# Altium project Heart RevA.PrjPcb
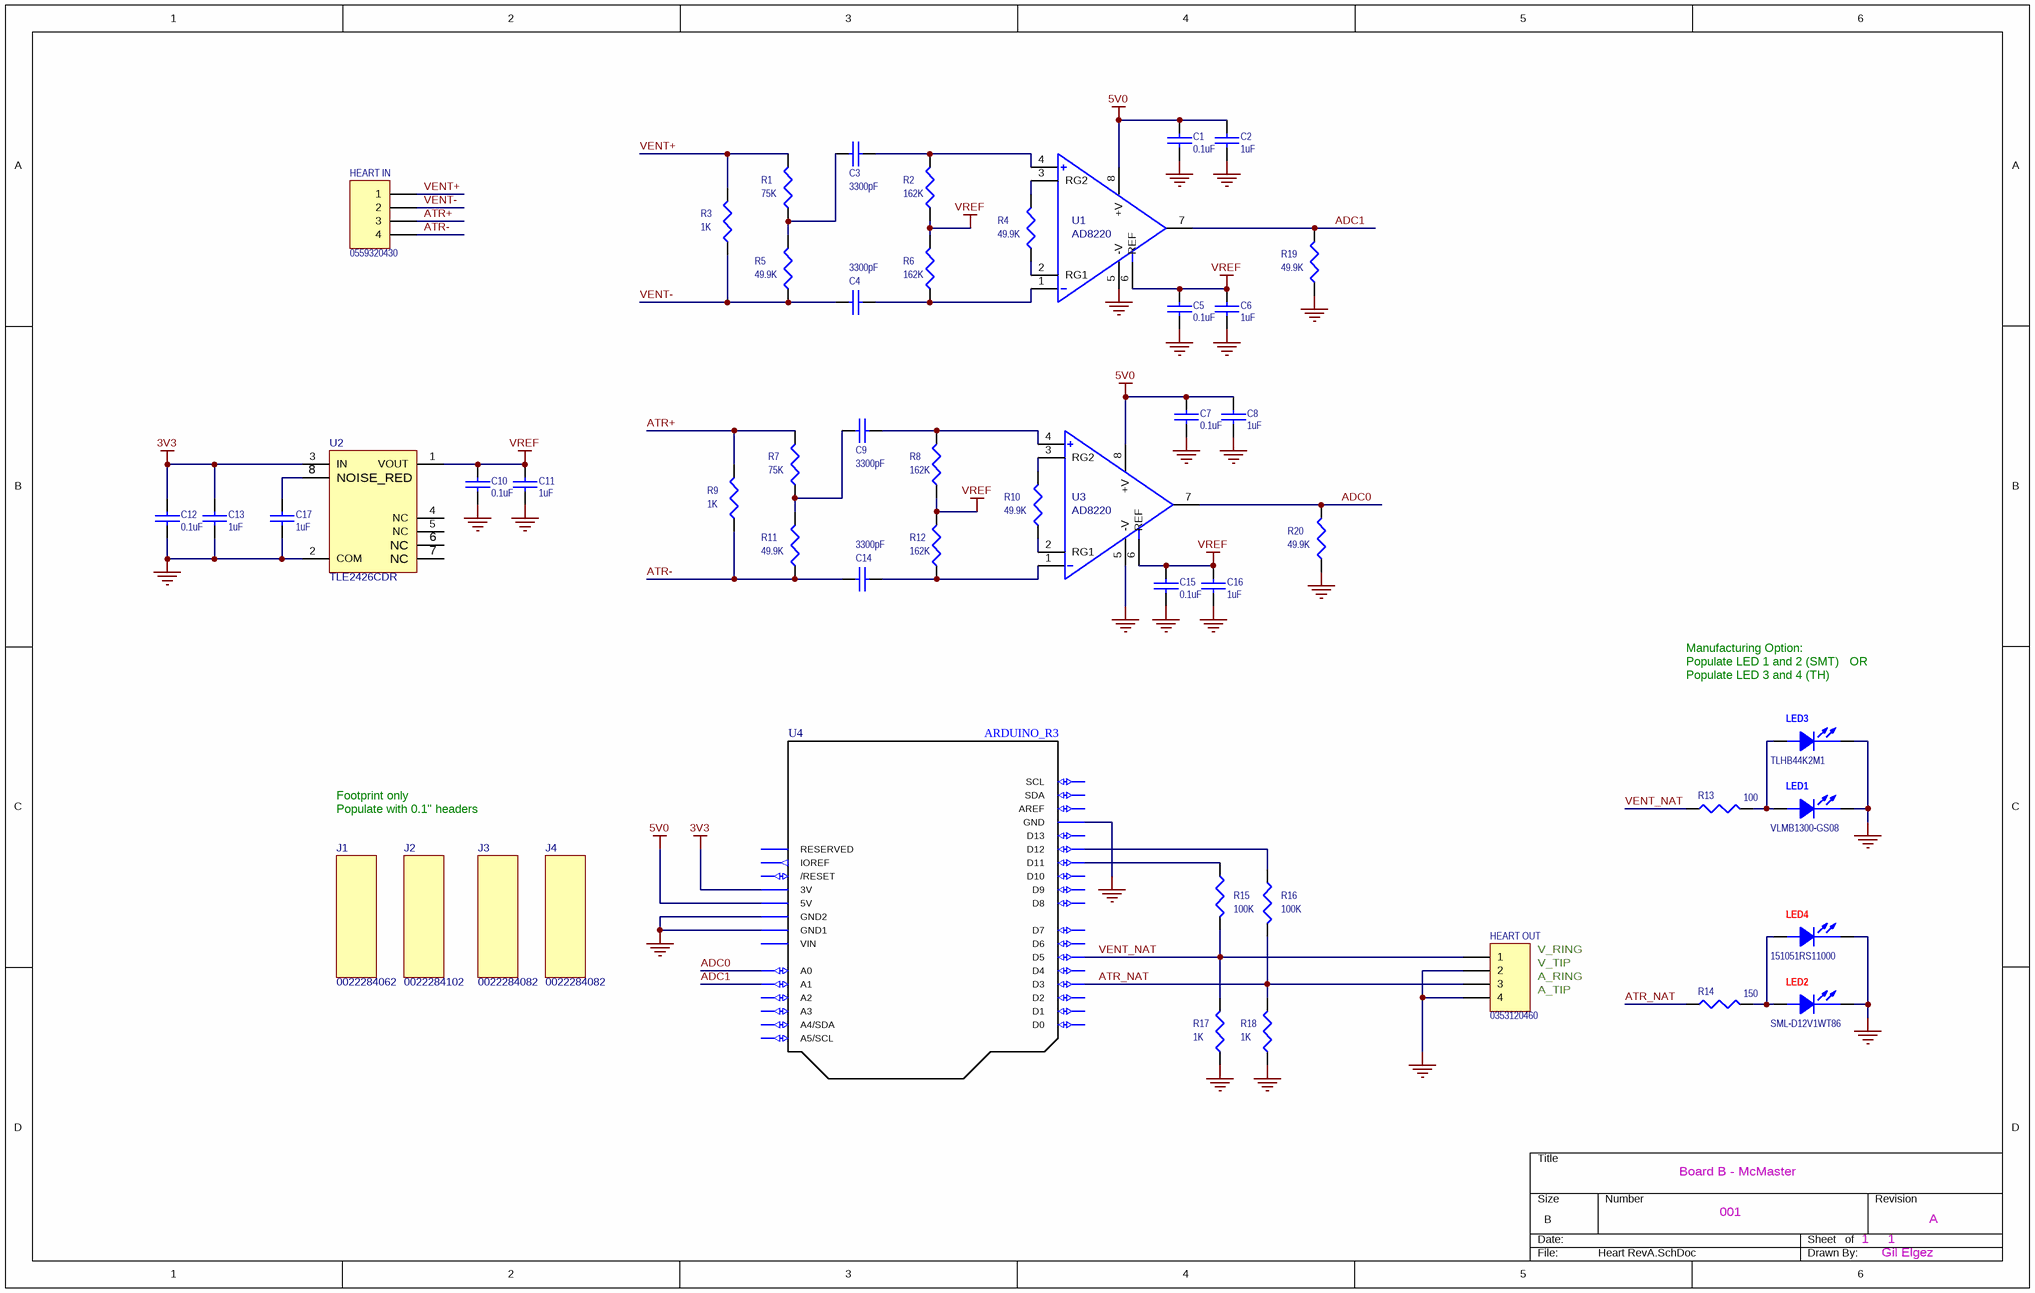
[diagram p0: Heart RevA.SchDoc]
1 sheet, 51 parts. Net scope: global (net labels, ports and power ports of the same name join across sheets).
Board file: Heart RevA.PcbDoc

## Sheet Heart RevA.SchDoc
size B; PageSetup: Record=PageOptions¦CenterHorizontal=True¦CenterVertical=True¦PrintScale=0.72¦XCorrection=1.00¦YCorrection=1.00¦PrintKind=0¦BorderSize=5000000¦LeftOffset=0¦BottomOffset=0¦Orientation=2¦PaperLength=1000¦PaperWidth=1000¦Scale=100¦PaperSource=7¦PrintQuality=-4¦MediaType=1¦DitherType=10¦PaperKind=Letter¦PrintScaleMode=1

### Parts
C1  0.1uF  [0603_N_1MM]
C2  1uF  [0603_N]
C3  3300pF  [0603_N]
C4  3300pF  [0603_N]
C5  0.1uF  [0603_N_1MM]
C6  1uF  [0603_N]
C7  0.1uF  [0603_N_1MM]
C8  1uF  [0603_N]
C9  3300pF  [0603_N]
C10  0.1uF  [0603_N_1MM]
C11  1uF  [0603_N]
C12  0.1uF  [0603_N_1MM]
C13  1uF  [0603_N]
C14  3300pF  [0603_N]
C15  0.1uF  [0603_N_1MM]
C16  1uF  [0603_N]
C17  1uF  [0603_N]
HEART_IN  0559320430  [B4B-PH-K-S]
HEART_OUT  0353120460  [B4B-XH-A]
J1  0022284062  [LHS-06-TS_OUTLINE]
J2  0022284102  [LHS-10-TS_OUTLINE]
J3  0022284082  [LHS-08-TS_OUTLINE]
J4  0022284082  [LHS-08-TS_OUTLINE]
LED1  VLMB1300-GS08  [LED_0603]
LED2  SML-D12V1WT86  [LED_0603]
LED3  TLHB44K2M1  [LED_5mm]
LED4  151051RS11000  [LED_5mm]
R1  75K  [0603_N_RES]
R2  162K  [0603_N_RES]
R3  1K  [0603_N_RES]
R4  49.9K  [0603_N_RES]
R5  49.9K  [0603_N_RES]
R6  162K  [0603_N_RES]
R7  75K  [0603_N_RES]
R8  162K  [0603_N_RES]
R9  1K  [0603_N_RES]
R10  49.9K  [0603_N_RES]
R11  49.9K  [0603_N_RES]
R12  162K  [0603_N_RES]
R13  100  [0603_N_RES]
R14  150  [0603_N_RES]
R15  100K  [0603_N_RES]
R16  100K  [0603_N_RES]
R17  1K  [0603_N_RES]
R18  1K  [0603_N_RES]
R19  49.9K  [0603_N_RES]
R20  49.9K  [0603_N_RES]
U1  AD8220  [MSOP8_0.65mm_DGK]
U2  TLE2426CDR  [SOIC8_SMTC]
U3  AD8220  [MSOP8_0.65mm_DGK]
U4  ARDUINO_R3  [ARDUINOR3]

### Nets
3V3: C12.2 C13.2 U2.3(IN) U4.3V
5V0: C1.2 C2.2 C7.2 C8.2 U1.8(+V) U3.8(+V) U4.5V
GND: C1.1 C2.1 C5.1 C6.1 C7.1 C8.1 C10.1 C11.1 C12.1 C13.1 C15.1 C16.1 C17.1 HEART_OUT.2 HEART_OUT.4 LED1.K(CATHODE) LED2.K(CATHODE) LED3.K(CATHODE) LED4.K(CATHODE) R17.1 R18.1 R19.1 R20.1 U1.5(-V) U2.2(COM) U3.5(-V) U4.GND U4.GND1 U4.GND2
VREF: C5.2 C6.2 C10.2 C11.2 C15.2 C16.2 R2.1 R6.2 R8.1 R12.2 U1.6(REF) U2.1(VOUT) U3.6(REF)
ADC0: R20.2 U3.7(OUT) U4.A0
ADC1: R19.2 U1.7(OUT) U4.A1
ATR+: HEART_IN.3 R7.2 R9.2
ATR-: C14.1 HEART_IN.4 R9.1 R11.1
ATR_NAT: HEART_OUT.3 R14.1 R16.2 R18.2 U4.D3
VENT+: HEART_IN.1 R1.2 R3.2
VENT-: C4.1 HEART_IN.2 R3.1 R5.1
VENT_NAT: HEART_OUT.1 R13.1 R15.2 R17.2 U4.D5
NetC3_1: C3.1 R1.1 R5.2
NetC3_2: C3.2 R2.2 U1.4(+IN)
NetC4_2: C4.2 R6.1 U1.1(-IN)
NetC9_1: C9.1 R7.1 R11.2
NetC9_2: C9.2 R8.2 U3.4(+IN)
NetC14_2: C14.2 R12.1 U3.1(-IN)
NetC17_2: C17.2 U2.8(NOISE_RED)
NetLED1_A: LED1.A(ANODE) LED3.A(ANODE) R13.2
NetLED2_A: LED2.A(ANODE) LED4.A(ANODE) R14.2
NetR4_1: R4.1 U1.2(RG1)
NetR4_2: R4.2 U1.3(RG2)
NetR10_1: R10.1 U3.2(RG1)
NetR10_2: R10.2 U3.3(RG2)
NetR15_1: R15.1 U4.D11
NetR16_1: R16.1 U4.D12

Not connected (* = marked no-connect by the designer): U2 4(NC) 5(NC) 6(NC) 7(NC); U4 A2 A3 A4(A4/SDA) A5(A5/SCL) AREF D0 D1 D2 D4 D6 D7 D8 D9 D10 D13 IOREF RESERVED RESET(/RESET) SCL SDA VIN

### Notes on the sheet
- (near LED3) Manufacturing Option:
  Populate LED 1 and 2 (SMT)   OR
  Populate LED 3 and 4 (TH)
- Footprint only
  Populate with 0.1" headers
- (near HEART_OUT) V_RING
- (near HEART_OUT) V_TIP
- (near HEART_OUT) A_RING
- (near HEART_OUT) A_TIP
- Board B - McMaster
- 001
- 1     1
- A
- Gil Elgez

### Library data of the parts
C1 C5 C7 C10 C12 C15 = CAP: CAP CER 0.1UF 50V X7R 0603; Manufacturer: Samsung; Value: CL10B104KB8NNNL
C2 C6 C8 C11 C13 C16 C17 = CAP: CAP CER 1UF 6.3V X7R 0603; Manufacturer: Samsung; Value: CL10B105KQ8NNNC
C3 C4 C9 C14 = CAP: CAP CER 3300PF 10V C0G/NP0 0603; Manufacturer: Würth Elektronik; Value: 885012006016
HEART_IN = Header 4: CONN HEADER VERT 4POS 2MM; Manufacturer: Molex
HEART_OUT = Header 4: CONN HEADER VERT 4POS 2.5MM; Manufacturer: Molex
J1 = SIP Header 6 Outline: CONN HEADER VERT 6POS 2.54MM; Manufacturer: Molex
J2 = SIP Header 10 Outline: CONN HEADER VERT 10POS 2.54MM; Manufacturer: Molex
J3 J4 = SIP Header 8 Outline: CONN HEADER VERT 8POS 2.54MM; Manufacturer: Molex
LED1 = LED_1: LED BLUE HIGHBRIGHT 0603 SMD; Manufacturer: Vishay
LED2 = LED_1: Red LED 2.2V 0603; Manufacturer: Rohm Semiconductor
LED3 = LED_1: LED BLUE CLEAR 3MM T/H; Manufacturer: TT Electronics/Optek Technology; Value: OVLBB4C7
LED4 = LED_1: LED RED CLEAR 3MM T/H; Manufacturer: TT Electronics/Optek Technology; Value: OVLBR4C7
R1 R7 = RES1: RES SMD 75K OHM 1% 1/10W 0603; Manufacturer: Yageo; Value: RC0603FR-0775KL
R2 R6 R8 R12 = RES1: RES SMD 162K OHM 1% 1/10W 0603; Manufacturer: Yageo; Value: RC0603FR-07162KL
R3 R9 R17 R18 = RES1: RES SMD 1K OHM 1% 1/10W 0603; Manufacturer: Yageo; Value: RC0603FR-071KL
R4 R5 R10 R11 R19 R20 = RES1: RES SMD 49.9K OHM 1% 1/10W 0603; Manufacturer: Yageo; Value: RC0603FR-0749K9L
R13 = RES1: RES SMD 100 OHM 1% 1/10W 0603; Manufacturer: Yageo; Value: RC0603FR-07100RL
R14 = RES1: RES SMD 150 OHM 1% 1/10W 0603; Manufacturer: Yageo; Value: RC0603FR-07150RL
R15 R16 = RES1: RES SMD 100K OHM 1% 1/10W 0603; Manufacturer: Yageo; Value: RC0603FR-07100KL
U1 U3 = AD8220: IC INST AMP 1 CIRCUIT 8MSOP; Manufacturer: Analog Devices Inc.; Value: AD8220ARMZ-R7
U2 = TLE2426: IC VREF GND REF 2.0V 1% 8SOIC; Manufacturer: Texas Instruments
U4 = ARDUINO_R3: Arduino R3 Shield

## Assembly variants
Production: not fitted LED1 LED2 U4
